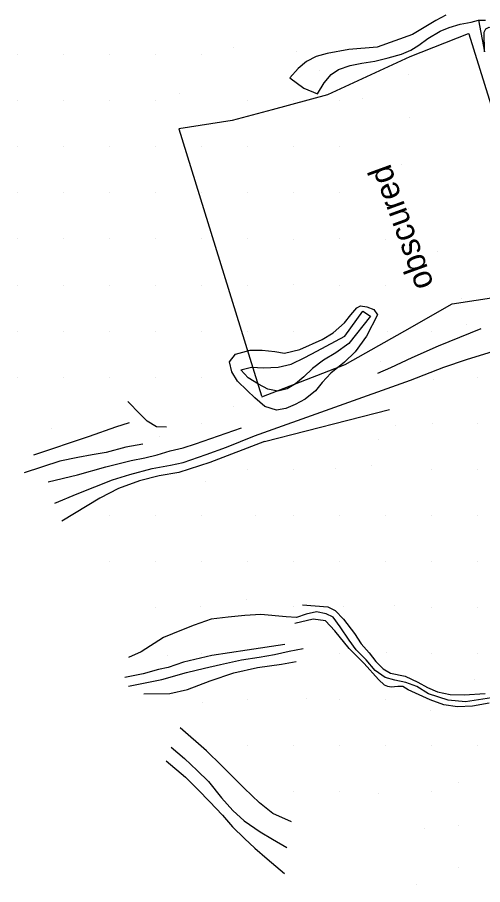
# Model space of a CAD drawing. Extents: x 524772 to 528246, y 273285 to 283088.
# Drawn here: x 527738.7 to 527837.2, y 274037.4 to 274221.1 of the extents above; entities that cross this region are included whole.
import ezdxf

# ---------------------------------------------------------------- set-up
doc = ezdxf.new("R2010")
doc.units = 0
for name, color, linetype in [('Old_Level_12', 7, 'Continuous'), ('PH Exist DTM Breakline', 7, 'Continuous'), ('PH Exist DTM Point', 7, 'Continuous')]:
    doc.layers.add(name, color=color, linetype=linetype)

msp = doc.modelspace()

# ---------------------------------------------------------------- linework, layer by layer
at = {"layer": 'Old_Level_12'}
msp.add_lwpolyline([(527790.41, 274140.76), (527808.09, 274147.58), (527820.7, 274154.72), (527830.77, 274160.45), (527840.94, 274162.02), (527847.27, 274161.91), (527850.38, 274161.86), (527854.98, 274160.99), (527843.32, 274188.73), (527834.36, 274217.55), (527834.17, 274217.65), (527821.77, 274212.77), (527804.33, 274204.71), (527792.62, 274201.51), (527784.15, 274199.26), (527772.83, 274197.49), (527790.39, 274140.96)], dxfattribs=at)
at = {"layer": 'PH Exist DTM Breakline'}
for points in [[(527829.4, 274221.58), (527827.28, 274220.45), (527822.35, 274217.52), (527814.9, 274214.8), (527808.88, 274214.29), (527804.27, 274213.51), (527801.96, 274212.85), (527799.88, 274211.77), (527798.15, 274210.31), (527796.34, 274208.32), (527799.31, 274206.1), (527802.2, 274204.95), (527803.64, 274207.25), (527805.1, 274209.05), (527806.71, 274210.07), (527809.14, 274210.95), (527811.65, 274211.42), (527814.34, 274211.87), (527817.22, 274212.54), (527820.02, 274213.32), (527822.02, 274214.16), (527823.7, 274215.23), (527825.59, 274216.63), (527828.21, 274218.19), (527830.1, 274219.02), (527832.45, 274219.68), (527834.81, 274220.14), (527836.36, 274220.57), (527837.84, 274220.51)], [(527836.36, 274220.57), (527837.59, 274213.82), (527837.52, 274217.97), (527837.9, 274218.67), (527838.57, 274219.03), (527839.6, 274218.7), (527840.74, 274217.1), (527844.6, 274207.7), (527849.16, 274194.23), (527852.29, 274184.32)], [(527814.95, 274158.12), (527812.64, 274153.61), (527810.21, 274150.25), (527807.93, 274148.07), (527805.04, 274145.73), (527803.24, 274143.8), (527801.77, 274142.04), (527799.59, 274140.24), (527797.5, 274139.1), (527795.53, 274138.25), (527793.56, 274137.94), (527791.08, 274138.71), (527788.92, 274140.5), (527787.33, 274142.08), (527785.3, 274144.07), (527784.08, 274146.03), (527783.58, 274148.17), (527784.84, 274149.77), (527787.93, 274150.61), (527790.52, 274150.64), (527793.17, 274150.32), (527795.26, 274149.99), (527798.5, 274150.76), (527803.22, 274152.91), (527805.55, 274154.3), (527807.93, 274156.41), (527809.27, 274158.13), (527810.54, 274159.62), (527811.36, 274160.03), (527812.7, 274159.78), (527814.16, 274159.24), (527814.95, 274158.12)], [(527813.44, 274157.83), (527808.89, 274152.06), (527806.09, 274150.05), (527803.49, 274148.49), (527801.17, 274146.73), (527799.34, 274144.99), (527797.57, 274143.5), (527795.8, 274142.47), (527793.8, 274141.91), (527791.71, 274142.36), (527789.75, 274143.39), (527787.54, 274144.8), (527786.01, 274146.43), (527788.22, 274147.03), (527790.82, 274146.88), (527793.91, 274147.02), (527796.65, 274147.64), (527799.54, 274149.07), (527802.09, 274150.44), (527808, 274153.61), (527811.8, 274158.88), (527813.44, 274157.83)], [(527836.82, 274155.18), (527827.79, 274151.48), (527822.22, 274149.03), (527817.66, 274146.9), (527814.94, 274145.71)], [(527788.88, 274132.45), (527821.92, 274144.25), (527829.01, 274147.01), (527833.77, 274148.64), (527837.64, 274149.82), (527842.77, 274151.4)], [(527770.25, 274134.29), (527768.13, 274134.35), (527766.16, 274135.56), (527764.63, 274137.08), (527762.06, 274139.74)], [(527791.02, 274131.28), (527817.48, 274138.08)], [(527742.11, 274128.47), (527753.92, 274132.43), (527759.49, 274134.39), (527762.44, 274135.27)], [(527745.19, 274122.7), (527751.4, 274124.24), (527757.39, 274125.91), (527762.77, 274127.22), (527765.64, 274127.79), (527768.25, 274128.48), (527771.03, 274129.29), (527773.8, 274129.93), (527776.41, 274130.8), (527786.14, 274134.16)], [(527765.23, 274130.68), (527761.62, 274130.07), (527757.43, 274128.94), (527754.52, 274128.44), (527751.45, 274127.88), (527747.67, 274127.08), (527740.09, 274124.64)], [(527746.57, 274118.19), (527751.31, 274120.17), (527758.81, 274123.16), (527762.47, 274124.26), (527767.19, 274125.58), (527771.12, 274126.27), (527773.78, 274126.81), (527778.62, 274128.52), (527782.92, 274130.08), (527788.88, 274132.45)], [(527791.02, 274131.28), (527779.41, 274126.82), (527772.88, 274124.72), (527768.69, 274124), (527764.49, 274122.91), (527760.05, 274121.3), (527756.13, 274119.28), (527748.06, 274114.4)], [(527799.03, 274096.66), (527804.44, 274096.23), (527805.95, 274095.45), (527807.75, 274093.61), (527810.06, 274090.61), (527811.49, 274088.41), (527813.17, 274086.51), (527814.55, 274084.69), (527816.12, 274083.13), (527817.7, 274082.23), (527820.78, 274081.56), (527823.5, 274080.32), (527825.52, 274079.18), (527827.62, 274078.22), (527830.33, 274077.68), (527833.3, 274077.61), (527837.74, 274077.89)], [(527839.08, 274076.98), (527833.6, 274076.11), (527829.9, 274076.45), (527825.74, 274077.84), (527823.3, 274079.34), (527820.95, 274080.24), (527818.62, 274080.68), (527816.55, 274081.29), (527814.45, 274082.78), (527812.52, 274085.02), (527810.43, 274087.15), (527808.9, 274089.16), (527807.02, 274092.04), (527805.55, 274094.05), (527804.05, 274094.8), (527802, 274095.17), (527799.82, 274094.7), (527797.76, 274093.97), (527795.61, 274094.14), (527790.23, 274094.6), (527786.82, 274094.39), (527783.29, 274094.06), (527779.69, 274093.61), (527776.09, 274092.36), (527773.42, 274091.28), (527769.64, 274089.78), (527764.9, 274086.75), (527762.21, 274085.52)], [(527838.59, 274075.83), (527835.04, 274075.23), (527831.91, 274075.07), (527828.99, 274075.5), (527826.09, 274076.53), (527823.02, 274077.93), (527821.4, 274078.7), (527820.32, 274079.35), (527819.23, 274079.37), (527817.8, 274079.24), (527817.13, 274079.35), (527816.41, 274079.67), (527815.17, 274080.86), (527812.08, 274084.24), (527808.91, 274087.42), (527805.9, 274091.17), (527803.94, 274093.28), (527801.31, 274093.63), (527797.43, 274092.69)], [(527795.3, 274088.26), (527787.34, 274087.09), (527779.87, 274085.95), (527773.83, 274084.53), (527770.63, 274083.42), (527768.54, 274082.95), (527765.3, 274082.09), (527761.4, 274081.27)], [(527762.19, 274079.43), (527769.28, 274080.86), (527774.46, 274082.33), (527778.32, 274083.27), (527781.66, 274084.03), (527786.12, 274085.02), (527789.9, 274085.58), (527793.11, 274086.16), (527796.23, 274086.84), (527799.2, 274087.43)], [(527765.41, 274077.84), (527770.98, 274077.91), (527774.66, 274078.72), (527779.46, 274080.56), (527784.54, 274082.3), (527789.55, 274083.37), (527794.62, 274084.11), (527797.69, 274084.65)], [(527796.73, 274050.71), (527792.79, 274052.46), (527789.95, 274054.76), (527786.69, 274057.85), (527781.86, 274062.62), (527778.7, 274065.72), (527773.16, 274070.63)], [(527771.26, 274066.51), (527774.06, 274064.09), (527776.75, 274061.55), (527779.16, 274059.23), (527781.9, 274055.82), (527784.31, 274053.08), (527786.66, 274050.94), (527790.07, 274048.59), (527792.73, 274047.02), (527795.72, 274045.27)], [(527770.17, 274063.59), (527774.25, 274060.14), (527776.98, 274057.49), (527779.38, 274054.99), (527782.1, 274052.09), (527784.25, 274049.62), (527786.8, 274047.18), (527788.98, 274045.13), (527791.54, 274042.84), (527795.26, 274039.76)]]:
    msp.add_lwpolyline(points, dxfattribs=at)
at = {"layer": 'PH Exist DTM Point'}
for p, q in [((527784.49, 274214.74), (527784.49, 274214.74)), ((527797.71, 274213.96), (527797.71, 274213.96)), ((527738.65, 274213.19), (527738.65, 274213.19)), ((527748.4, 274213.19), (527748.4, 274213.19)), ((527758.16, 274213.19), (527758.16, 274213.19)), ((527767.91, 274213.19), (527767.91, 274213.19)), ((527777.67, 274213.19), (527777.67, 274213.19)), ((527802.56, 274209.89), (527802.56, 274209.89)), ((527821.57, 274209.06), (527821.57, 274209.06)), ((527773.02, 274204.98), (527773.02, 274204.98)), ((527738.65, 274203.44), (527738.65, 274203.44)), ((527748.4, 274203.44), (527748.4, 274203.44)), ((527758.16, 274203.44), (527758.16, 274203.44)), ((527767.91, 274203.44), (527767.91, 274203.44)), ((527787.42, 274203.44), (527787.42, 274203.44)), ((527797.17, 274203.44), (527797.17, 274203.44)), ((527806.93, 274203.44), (527806.93, 274203.44)), ((527811.67, 274203.91), (527811.67, 274203.91)), ((527821.77, 274199.9), (527821.77, 274199.9)), ((527738.65, 274193.69), (527738.65, 274193.69)), ((527748.4, 274193.69), (527748.4, 274193.69)), ((527758.16, 274193.69), (527758.16, 274193.69)), ((527767.91, 274193.69), (527767.91, 274193.69)), ((527777.67, 274193.69), (527777.67, 274193.69)), ((527787.42, 274193.69), (527787.42, 274193.69)), ((527797.17, 274193.69), (527797.17, 274193.69)), ((527806.93, 274193.69), (527806.93, 274193.69)), ((527819.98, 274190.01), (527819.98, 274190.01)), ((527738.65, 274183.93), (527738.65, 274183.93)), ((527748.4, 274183.93), (527748.4, 274183.93)), ((527758.16, 274183.93), (527758.16, 274183.93)), ((527767.91, 274183.93), (527767.91, 274183.93)), ((527777.68, 274183.96), (527777.68, 274183.96)), ((527787.42, 274183.93), (527787.42, 274183.93)), ((527797.17, 274183.93), (527797.17, 274183.93)), ((527806.93, 274183.93), (527806.93, 274183.93)), ((527816.38, 274183.89), (527816.38, 274183.89)), ((527821.53, 274180.67), (527821.53, 274180.67)), ((527738.65, 274174.18), (527738.65, 274174.18)), ((527748.4, 274174.18), (527748.4, 274174.18)), ((527758.16, 274174.18), (527758.16, 274174.18)), ((527767.91, 274174.18), (527767.91, 274174.18)), ((527777.67, 274174.18), (527777.67, 274174.18)), ((527787.42, 274174.18), (527787.42, 274174.18)), ((527797.2, 274174.16), (527797.2, 274174.16)), ((527806.93, 274174.18), (527806.93, 274174.18)), ((527816.66, 274174.17), (527816.66, 274174.17)), ((527827.63, 274171.59), (527827.63, 274171.59)), ((527738.65, 274164.42), (527738.65, 274164.42)), ((527748.4, 274164.42), (527748.4, 274164.42)), ((527758.16, 274164.42), (527758.16, 274164.42)), ((527767.91, 274164.42), (527767.91, 274164.42)), ((527777.65, 274164.4), (527777.65, 274164.4)), ((527787.42, 274164.42), (527787.42, 274164.42)), ((527797.16, 274164.46), (527797.16, 274164.46)), ((527806.93, 274164.42), (527806.93, 274164.42)), ((527816.7, 274164.43), (527816.7, 274164.43)), ((527825.8, 274164.04), (527825.8, 274164.04)), ((527832.82, 274161.63), (527832.82, 274161.63)), ((527738.65, 274154.67), (527738.65, 274154.67)), ((527748.4, 274154.67), (527748.4, 274154.67)), ((527758.16, 274154.65), (527758.16, 274154.65)), ((527767.91, 274154.67), (527767.91, 274154.67)), ((527777.67, 274154.67), (527777.67, 274154.67)), ((527787.42, 274154.67), (527787.42, 274154.67)), ((527797.16, 274154.65), (527797.16, 274154.65)), ((527817.15, 274154.66), (527817.15, 274154.66)), ((527826.43, 274154.67), (527826.43, 274154.67)), ((527833.77, 274156.14), (527833.77, 274156.14)), ((527815.66, 274148.21), (527815.66, 274148.21)), ((527738.65, 274144.92), (527738.65, 274144.92)), ((527748.4, 274144.92), (527748.4, 274144.92)), ((527758.15, 274144.94), (527758.15, 274144.94)), ((527767.91, 274144.92), (527767.91, 274144.92)), ((527777.68, 274144.94), (527777.68, 274144.94)), ((527826.75, 274144.31), (527826.75, 274144.31)), ((527836.2, 274144.94), (527836.2, 274144.94)), ((527784.46, 274138.67), (527784.46, 274138.67)), ((527777.67, 274135.16), (527777.67, 274135.16)), ((527818.71, 274134.57), (527818.71, 274134.57)), ((527826.54, 274135.15), (527826.54, 274135.15)), ((527836.19, 274135.16), (527836.19, 274135.16)), ((527745.83, 274134.08), (527745.83, 274134.08)), ((527768.83, 274132.25), (527768.83, 274132.25)), ((527815.06, 274131.78), (527815.06, 274131.78)), ((527787.42, 274125.41), (527787.42, 274125.41)), ((527797.17, 274125.41), (527797.17, 274125.41)), ((527806.05, 274125.63), (527806.05, 274125.63)), ((527813.62, 274126.11), (527813.62, 274126.11)), ((527826.38, 274125.39), (527826.38, 274125.39)), ((527836.19, 274125.39), (527836.19, 274125.39)), ((527778.58, 274122.74), (527778.58, 274122.74)), ((527758.16, 274115.66), (527758.16, 274115.66)), ((527767.91, 274115.66), (527767.91, 274115.66)), ((527777.67, 274115.66), (527777.67, 274115.66)), ((527789.05, 274115.68), (527789.05, 274115.68)), ((527797.17, 274115.66), (527797.17, 274115.66)), ((527806.93, 274115.66), (527806.93, 274115.66)), ((527816.68, 274115.66), (527816.68, 274115.66)), ((527826.43, 274115.66), (527826.43, 274115.66)), ((527836.17, 274115.65), (527836.17, 274115.65)), ((527758.16, 274105.9), (527758.16, 274105.9)), ((527767.91, 274105.9), (527767.91, 274105.9)), ((527777.67, 274105.9), (527777.67, 274105.9)), ((527787.42, 274105.9), (527787.42, 274105.9)), ((527797.2, 274105.89), (527797.2, 274105.89)), ((527806.93, 274105.9), (527806.93, 274105.9)), ((527816.69, 274105.93), (527816.69, 274105.93)), ((527826.43, 274105.9), (527826.43, 274105.9)), ((527836.19, 274105.9), (527836.19, 274105.9)), ((527787.12, 274097.74), (527787.12, 274097.74)), ((527767.91, 274096.15), (527767.91, 274096.15)), ((527777.49, 274096.26), (527777.49, 274096.26)), ((527797.1, 274096.4), (527797.1, 274096.4)), ((527807.66, 274096.38), (527807.66, 274096.38)), ((527818.48, 274096.59), (527818.48, 274096.59)), ((527826.43, 274096.15), (527826.43, 274096.15)), ((527836.19, 274096.15), (527836.19, 274096.15)), ((527816.93, 274086.61), (527816.93, 274086.61)), ((527770.47, 274085.88), (527770.47, 274085.88)), ((527777.67, 274086.4), (527777.67, 274086.4)), ((527806.93, 274086.4), (527806.93, 274086.4)), ((527826.43, 274086.4), (527826.43, 274086.4)), ((527836.19, 274086.4), (527836.19, 274086.4)), ((527835.39, 274080.89), (527835.39, 274080.89)), ((527777.9, 274075.89), (527777.9, 274075.89)), ((527787.42, 274076.64), (527787.42, 274076.64)), ((527799.93, 274076.88), (527799.93, 274076.88)), ((527806.93, 274076.64), (527806.93, 274076.64)), ((527816.68, 274076.64), (527816.68, 274076.64)), ((527826.13, 274074.31), (527826.13, 274074.31)), ((527787.44, 274066.89), (527787.44, 274066.89)), ((527797.15, 274066.88), (527797.15, 274066.88)), ((527806.93, 274066.89), (527806.93, 274066.89)), ((527816.7, 274066.88), (527816.7, 274066.88)), ((527826.43, 274066.89), (527826.43, 274066.89)), ((527836.19, 274066.89), (527836.19, 274066.89)), ((527832, 274059), (527832, 274059)), ((527797.17, 274057.14), (527797.17, 274057.14)), ((527806.93, 274057.14), (527806.93, 274057.14)), ((527815.08, 274056.73), (527815.08, 274056.73)), ((527826.43, 274057.14), (527826.43, 274057.14)), ((527832, 274050.01), (527832, 274050.01)), ((527824.79, 274049.25), (527824.79, 274049.25)), ((527832, 274041), (527832, 274041)), ((527823.27, 274037.39), (527823.27, 274037.39))]:
    msp.add_line(p, q, dxfattribs=at)

# ---------------------------------------------------------------- texts
at = {"layer": 'Old_Level_12'}
msp.add_text('obscured', height=5, rotation=110, dxfattribs=at).set_placement((527826.93, 274164.49))

doc.saveas('drawing.dxf')
